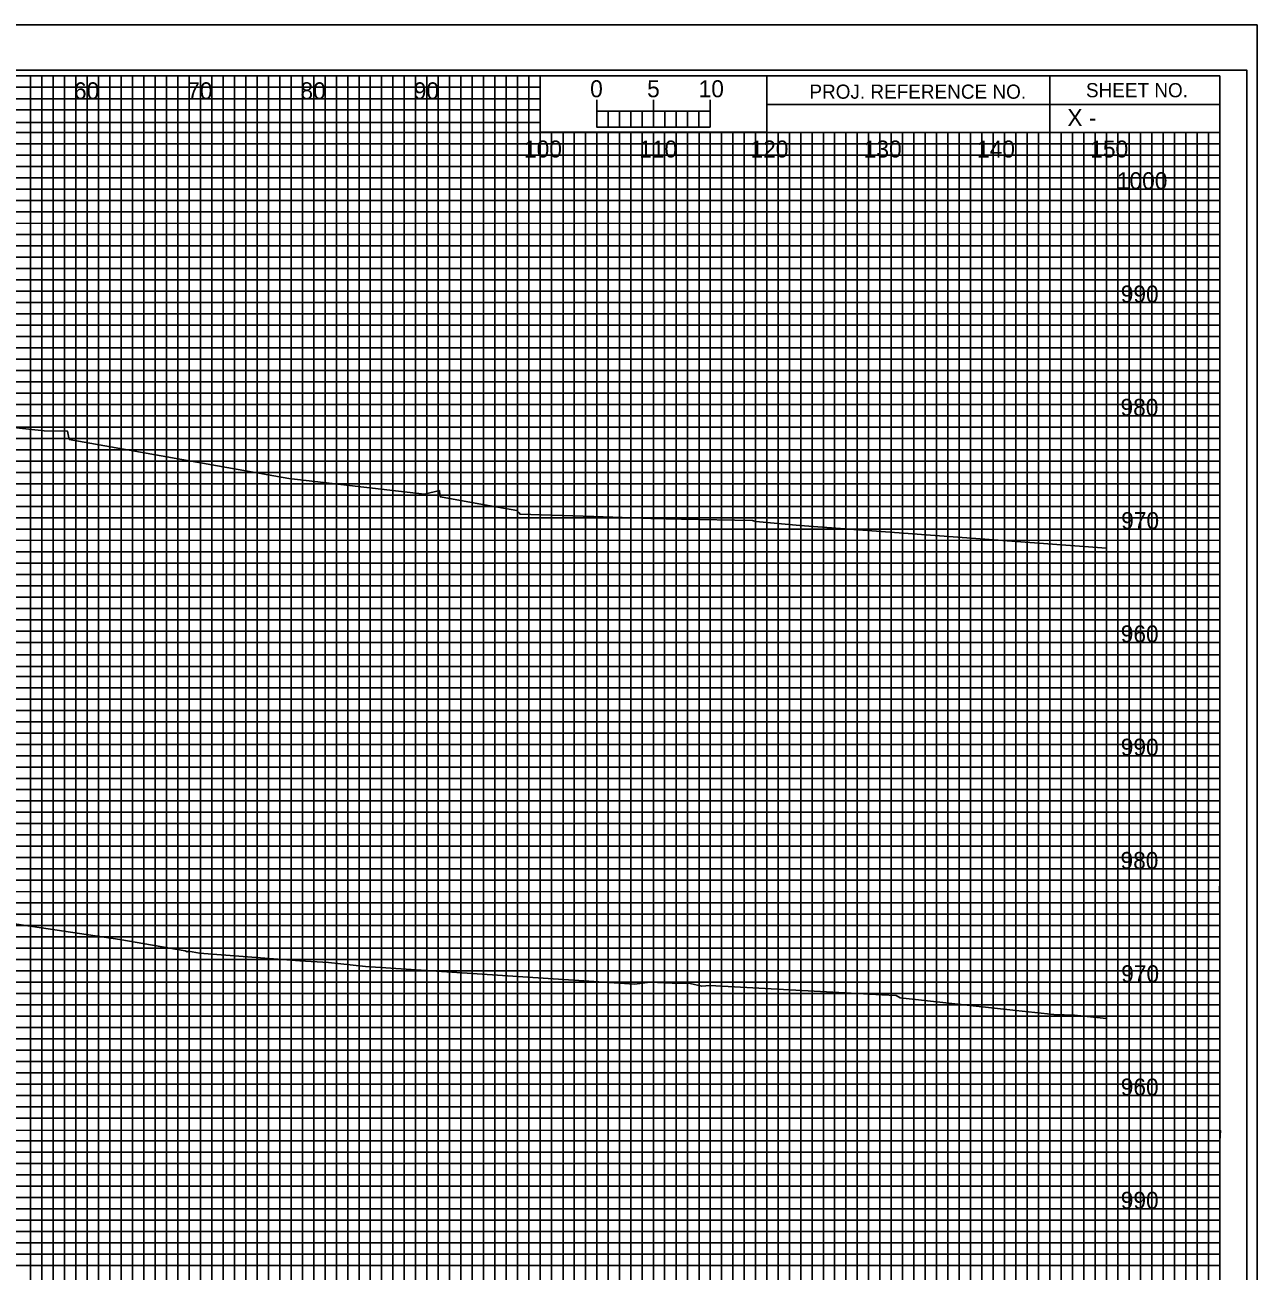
# Model space of a CAD drawing. Extents: x -13 to 760, y -5 to 1491.
# Drawn here: x 651.2 to 760, y 423.5 to 533.5 of the extents above; entities that cross this region are included whole.
import ezdxf

# ---------------------------------------------------------------- set-up
doc = ezdxf.new("R2010")
doc.units = 0
for name, color, linetype in [('Exist XS Ground Line', 7, 'Continuous'), ('Prop XS Elevation Labels', 7, 'Continuous'), ('Prop XS Offset Labels', 7, 'Continuous'), ('Sheet Cross Section CELL', 7, 'Continuous'), ('Sheet Cross Section Grid Major CELL', 7, 'Continuous'), ('Sheet Cross Section Grid Middle CELL', 7, 'Continuous'), ('Sheet Cross Section Grid Minor 1 CELL', 7, 'Continuous'), ('Sheet Cross Section Grid Minor 2 CELL', 7, 'Continuous'), ('Sheet Cross Section Scale CELL', 7, 'Continuous'), ('Sheet Cutting Line CELL', 7, 'Continuous'), ('Sheet DOT Grid CELL', 7, 'Continuous'), ('Sheet Plot Border Inside CELL', 7, 'Continuous'), ('Sheet Plot Border Outside CELL', 7, 'Continuous')]:
    doc.layers.add(name, color=color, linetype=linetype)

msp = doc.modelspace()

# ---------------------------------------------------------------- linework, layer by layer
at = {"layer": 'Exist XS Ground Line'}
for points in [[(650.47, 497.95), (652.91, 497.68), (654.95, 497.65), (655.11, 496.92), (655.12, 496.92), (674.49, 493.47), (686.48, 492.09), (687.8, 492.4), (687.85, 492.05), (687.89, 491.84), (691.27, 491.24), (694.63, 490.64), (694.64, 490.64), (694.85, 490.43), (694.93, 490.31), (701.44, 490.1), (706.46, 489.93), (709.19, 489.88), (715.46, 489.75), (715.74, 489.68), (719.63, 489.33), (746.7, 487.32)], [(650.47, 497.95), (652.91, 497.68), (654.95, 497.65), (655.11, 496.92), (655.12, 496.92), (674.49, 493.47), (686.48, 492.09), (687.8, 492.4), (687.85, 492.05), (687.89, 491.84), (691.27, 491.24), (694.63, 490.64), (694.64, 490.64), (694.85, 490.43), (694.93, 490.31), (701.44, 490.1), (706.46, 489.93), (709.19, 489.88), (715.46, 489.75), (715.74, 489.68), (719.63, 489.33), (746.7, 487.32)], [(644.72, 454.97), (659.59, 452.77), (665.36, 451.78), (665.52, 451.68), (665.65, 451.73), (666.61, 451.57), (675.47, 450.9), (678.02, 450.73), (681.26, 450.39), (705.04, 448.82), (706.4, 449), (708.35, 448.93), (709.95, 448.9), (710.96, 448.65), (711.67, 448.72), (726.88, 447.89), (728.12, 447.83), (728.47, 447.62), (738.7, 446.51), (742.05, 446.16), (743.88, 446.08), (744.99, 445.97), (746.7, 445.8)], [(644.72, 454.97), (659.59, 452.77), (665.36, 451.78), (665.52, 451.68), (665.65, 451.73), (666.61, 451.57), (675.47, 450.9), (678.02, 450.73), (681.26, 450.39), (705.04, 448.82), (706.4, 449), (708.35, 448.93), (709.95, 448.9), (710.96, 448.65), (711.67, 448.72), (726.88, 447.89), (728.12, 447.83), (728.47, 447.62), (738.7, 446.51), (742.05, 446.16), (743.88, 446.08), (744.99, 445.97), (746.7, 445.8)]]:
    msp.add_lwpolyline(points, dxfattribs=at)
at = {"layer": 'Sheet Cross Section CELL'}
for p, q in [((741.7, 529), (741.7, 524)), ((741.7, 524), (741.7, 529)), ((716.7, 526.5), (716.7, 524)), ((756.7, 526.49), (716.7, 526.49)), ((716.7, 524), (756.7, 524))]:
    msp.add_line(p, q, dxfattribs=at)
for points in [[(756.7, 529), (436.7, 529), (436.7, 319), (756.7, 319)], [(716.7, 529), (696.7, 529), (696.7, 524.03), (716.7, 524.03)], [(756.7, 529), (716.7, 529), (716.7, 524), (756.7, 524)]]:
    msp.add_lwpolyline(points, close=True, dxfattribs=at)
at = {"layer": 'Sheet Cross Section Grid Major CELL'}
for p, q in [((666.7, 529), (656.7, 529)), ((656.7, 529), (656.7, 319)), ((666.7, 319), (666.7, 529)), ((686.7, 529), (676.7, 529)), ((676.7, 529), (676.7, 319)), ((686.7, 319), (686.7, 529)), ((696.7, 529), (696.7, 319)), ((706.7, 319), (706.7, 524)), ((726.7, 524), (716.7, 524)), ((716.7, 524), (716.7, 319)), ((726.7, 319), (726.7, 524)), ((746.7, 524), (736.7, 524)), ((736.7, 524), (736.7, 319)), ((746.7, 319), (746.7, 524))]:
    msp.add_line(p, q, dxfattribs=at)
for points in [[(436.7, 519), (756.7, 519), (756.7, 509), (436.7, 509)], [(436.7, 499), (756.7, 499), (756.7, 489), (436.7, 489)], [(436.7, 479), (756.7, 479), (756.7, 469), (436.7, 469)], [(436.7, 459), (756.7, 459), (756.7, 449), (436.7, 449)], [(436.7, 439), (756.7, 439), (756.7, 429), (436.7, 429)]]:
    msp.add_lwpolyline(points, dxfattribs=at)
at = {"layer": 'Sheet Cross Section Grid Middle CELL'}
for points in [[(651.7, 319), (651.7, 529), (661.7, 529), (661.7, 319)], [(671.7, 319), (671.7, 529), (681.7, 529), (681.7, 319)], [(691.7, 319), (691.7, 529), (696.63, 529), (696.7, 529), (696.7, 524), (701.69, 524), (701.69, 319)], [(436.7, 524), (711.7, 524)], [(711.7, 319), (711.7, 524), (721.7, 524), (721.7, 319)], [(731.7, 319), (731.7, 524), (741.7, 524), (741.7, 319)], [(751.7, 319), (751.7, 524)], [(436.7, 504), (756.7, 504), (756.7, 514), (436.7, 514)], [(436.7, 484), (756.7, 484), (756.7, 494), (436.7, 494)], [(436.7, 464), (756.7, 464), (756.7, 474), (436.7, 474)], [(436.7, 444), (756.7, 444), (756.7, 454), (436.7, 454)], [(436.7, 424), (756.7, 424), (756.7, 434), (436.7, 434)]]:
    msp.add_lwpolyline(points, dxfattribs=at)
at = {"layer": 'Sheet Cross Section Grid Minor 1 CELL'}
for p, q in [((436.7, 528), (696.7, 528)), ((696.7, 528), (696.7, 526.98)), ((696.7, 526.98), (436.7, 526.98)), ((436.7, 526), (696.7, 526)), ((696.7, 526), (696.7, 524.89)), ((696.7, 524.89), (436.7, 524.89)), ((436.7, 523), (756.7, 523))]:
    msp.add_line(p, q, dxfattribs=at)
for points in [[(436.7, 522), (706.7, 522), (756.7, 522), (756.7, 521), (436.7, 521)], [(436.7, 520), (756.7, 520), (756.7, 518), (436.7, 518)], [(436.7, 517), (756.7, 517), (756.7, 516), (436.7, 515.98)], [(436.7, 515), (756.7, 515), (756.7, 513), (436.7, 513)], [(436.7, 512), (756.7, 512), (756.7, 511), (436.7, 511)], [(436.7, 510), (756.7, 510), (756.7, 508), (436.7, 508)], [(436.7, 507), (756.7, 507), (756.7, 506), (436.7, 506)], [(436.7, 505), (756.7, 505), (756.7, 503), (436.7, 503)], [(436.7, 502), (756.7, 502), (756.7, 501), (436.7, 501)], [(436.7, 500), (756.7, 500), (756.7, 498), (436.7, 498)], [(436.7, 497), (756.7, 497), (756.7, 496), (436.7, 496)], [(436.7, 495), (756.7, 495), (756.7, 492.95), (756.7, 492), (756.7, 491), (436.7, 491)], [(436.7, 493), (756.7, 493), (756.7, 492), (436.7, 492)], [(436.7, 490), (756.7, 490), (756.7, 488), (436.7, 488.03)], [(436.7, 488.03), (756.7, 488), (756.7, 487), (436.7, 487)], [(436.7, 486), (756.7, 486), (756.7, 485), (436.7, 485)], [(436.7, 483), (756.7, 483), (756.7, 482), (436.7, 482)], [(436.7, 481), (756.7, 481), (756.7, 480), (436.7, 480)], [(436.63, 477.89), (756.7, 477.89), (756.7, 476.88), (436.63, 476.88)], [(436.7, 476), (756.7, 476), (756.7, 475), (436.7, 475)], [(436.7, 473), (756.7, 473), (756.7, 472), (436.7, 472)], [(436.7, 471), (756.7, 471), (756.7, 470), (436.7, 470)], [(436.7, 468), (756.7, 468), (756.7, 467), (436.7, 467)], [(436.7, 466), (756.7, 466), (756.7, 465), (436.7, 465)], [(436.7, 463), (756.7, 463), (756.7, 462), (436.7, 462)], [(436.7, 461), (756.7, 461), (756.7, 460), (436.7, 460)], [(436.7, 458), (756.7, 458), (756.69, 456.98), (436.7, 457)], [(436.7, 456), (756.7, 456), (756.7, 455), (436.7, 455)], [(436.7, 453), (756.7, 453), (756.7, 452), (436.7, 452)], [(436.7, 451), (756.7, 451), (756.7, 450), (436.7, 450)], [(436.7, 448), (756.7, 448), (756.7, 447), (436.7, 447)], [(436.7, 446), (756.7, 446), (756.7, 445), (436.7, 445)], [(436.7, 443), (756.7, 443), (756.7, 442), (436.7, 442)], [(436.7, 441), (756.7, 441), (756.7, 440), (436.7, 440)], [(436.7, 438), (756.7, 438), (756.7, 437), (436.7, 437)], [(436.7, 435.99), (756.77, 435.91), (756.7, 435), (436.7, 435)], [(436.7, 433), (756.7, 433), (756.7, 432), (436.7, 432)], [(436.7, 431), (756.7, 431), (756.7, 430), (436.7, 430)], [(436.7, 428), (756.7, 428), (756.7, 427), (436.7, 427)], [(436.7, 426), (756.7, 426), (756.7, 425), (436.7, 425)]]:
    msp.add_lwpolyline(points, dxfattribs=at)
at = {"layer": 'Sheet Cross Section Grid Minor 2 CELL'}
for p, q in [((703.7, 524), (702.71, 524)), ((702.71, 524), (702.71, 319)), ((703.7, 319), (703.7, 524)), ((705.7, 524), (704.7, 524)), ((704.7, 524), (704.7, 319)), ((705.7, 319), (705.7, 524))]:
    msp.add_line(p, q, dxfattribs=at)
for points in [[(651.7, 319), (652.7, 319), (652.7, 529), (653.7, 529), (653.7, 319)], [(653.7, 319), (654.7, 319), (654.7, 529), (655.7, 529), (655.7, 319)], [(656.7, 319), (657.7, 319), (657.7, 529), (658.7, 529), (658.7, 319)], [(658.7, 319), (659.7, 319), (659.7, 529), (660.7, 529), (660.7, 319)], [(661.7, 319), (662.7, 319), (662.7, 529), (663.7, 529), (663.7, 319)], [(663.7, 319), (664.7, 319), (664.7, 529), (665.7, 529), (665.7, 319)], [(666.7, 319), (667.7, 319), (667.7, 529), (668.7, 529), (668.7, 319)], [(668.7, 319), (669.7, 319), (669.7, 529), (670.7, 529), (670.7, 319)], [(671.7, 319), (672.7, 319), (672.7, 529), (673.7, 529), (673.7, 319)], [(673.7, 319), (674.7, 319), (674.7, 529), (675.7, 529), (675.7, 319)], [(676.7, 319), (677.7, 319), (677.7, 529), (678.7, 529), (678.7, 319)], [(678.7, 319), (679.7, 319), (679.7, 529), (680.7, 529), (680.7, 319)], [(681.7, 319), (682.7, 319), (682.7, 529), (683.7, 529), (683.7, 319)], [(683.7, 319), (684.7, 319), (684.7, 529), (685.7, 529), (685.7, 319)], [(686.7, 319), (687.7, 319), (687.7, 529), (688.7, 529), (688.7, 319)], [(688.7, 319), (689.7, 319), (689.7, 529), (690.7, 529), (690.7, 319)], [(691.7, 319), (692.7, 319), (692.7, 529), (693.7, 529), (693.7, 319)], [(693.7, 319), (694.7, 319), (694.7, 529), (695.7, 529), (695.7, 319)], [(696.7, 319), (697.7, 319), (697.7, 524), (698.72, 524), (698.72, 319)], [(698.7, 319), (699.7, 319), (699.7, 524), (700.69, 524), (700.69, 319)], [(706.7, 319), (707.68, 319), (707.68, 524), (708.7, 524), (708.7, 319)], [(708.7, 319), (709.7, 319), (709.7, 524), (710.75, 524), (710.75, 319)], [(711.7, 319), (712.7, 319), (712.7, 524), (713.7, 524), (713.7, 319)], [(713.7, 319), (714.7, 319), (714.7, 524), (715.7, 524), (715.7, 319)], [(716.7, 319), (717.7, 319), (717.7, 524), (718.7, 524), (718.7, 319)], [(718.7, 319), (719.7, 319), (719.7, 524), (720.7, 524), (720.7, 319)], [(721.7, 319), (722.7, 319), (722.7, 524), (723.7, 524), (723.7, 319)], [(723.7, 319), (724.7, 319), (724.7, 524), (725.7, 524), (725.7, 319)], [(726.7, 319), (727.7, 319), (727.7, 524), (728.7, 524), (728.7, 319)], [(728.7, 319), (729.7, 319), (729.7, 524), (730.7, 524), (730.7, 319)], [(731.7, 319), (732.7, 319), (732.7, 524), (733.7, 524), (733.7, 319)], [(733.7, 319), (734.7, 319), (734.7, 524), (735.7, 524), (735.7, 319)], [(736.7, 319), (737.7, 319), (737.7, 524), (738.7, 524), (738.7, 319)], [(738.7, 319), (739.7, 319), (739.7, 524), (740.7, 524), (740.7, 319)], [(741.7, 319), (742.7, 319), (742.7, 524), (743.7, 524), (743.7, 319)], [(743.7, 319), (744.7, 319), (744.7, 524), (745.7, 524), (745.7, 319)], [(746.7, 319), (747.7, 319), (747.7, 524), (748.7, 524), (748.7, 319)], [(748.7, 319), (749.7, 319), (749.7, 524), (750.7, 524), (750.7, 319)], [(751.7, 319), (752.7, 319), (752.7, 524), (753.7, 524), (753.7, 319)], [(753.7, 319), (754.7, 319), (754.7, 524), (755.7, 524), (755.7, 319)]]:
    msp.add_lwpolyline(points, dxfattribs=at)
at = {"layer": 'Sheet Cross Section Scale CELL'}
for p, q in [((701.7, 524.49), (701.7, 526.9)), ((701.7, 525.9), (701.7, 526.9)), ((706.7, 524.49), (706.7, 526.9)), ((711.7, 524.49), (711.7, 526.9)), ((711.7, 525.9), (711.7, 526.9))]:
    msp.add_line(p, q, dxfattribs=at)
for points in [[(711.7, 525.9), (701.7, 525.9), (701.7, 524.49), (711.7, 524.49)], [(701.7, 525.9), (702.7, 525.9), (702.7, 524.49), (701.7, 524.49)], [(703.7, 525.9), (704.7, 525.9), (704.7, 524.49), (703.7, 524.49)], [(705.7, 525.9), (706.7, 525.9), (706.7, 524.49), (705.7, 524.49)], [(707.7, 525.9), (708.7, 525.9), (708.7, 524.49), (707.7, 524.49)], [(709.7, 525.9), (710.7, 525.9), (710.7, 524.49), (709.7, 524.49)]]:
    msp.add_lwpolyline(points, close=True, dxfattribs=at)
at = {"layer": 'Sheet Cutting Line CELL'}
msp.add_line((760, 533.5), (423.3, 533.5), dxfattribs=at)
at = {"layer": 'Sheet DOT Grid CELL'}
for p, q in [((656.7, 319), (656.7, 529)), ((666.7, 319), (666.7, 529)), ((676.7, 319), (676.7, 529)), ((686.7, 319), (686.7, 529)), ((696.7, 319), (696.7, 523.69)), ((706.7, 319), (706.7, 523.69)), ((716.7, 319), (716.7, 523.69)), ((726.7, 319), (726.7, 523.69)), ((736.7, 319), (736.7, 523.69)), ((746.7, 319), (746.7, 523.69)), ((436.7, 519), (756.7, 519)), ((436.7, 509), (756.7, 509)), ((436.7, 499), (756.7, 499)), ((436.7, 489), (756.7, 489)), ((436.7, 479), (756.7, 479)), ((436.7, 469), (756.7, 469)), ((436.7, 459), (756.7, 459)), ((436.7, 449), (756.7, 449)), ((436.7, 439), (756.7, 439)), ((436.7, 429), (756.7, 429))]:
    msp.add_line(p, q, dxfattribs=at)
at = {"layer": 'Sheet Plot Border Inside CELL'}
msp.add_lwpolyline([(425.9, 318.5), (759.1, 318.5), (759.1, 529.5), (425.9, 529.5)], close=True, dxfattribs=at)
at = {"layer": 'Sheet Plot Border Outside CELL'}
msp.add_lwpolyline([(423.3, 314.5), (760, 314.5), (760, 533.5), (423.3, 533.5)], close=True, dxfattribs=at)

# ---------------------------------------------------------------- texts
at = {"layer": 'Prop XS Elevation Labels'}
for s, p in [('1000', (747.62, 519)), ('990', (747.96, 509)), ('980', (747.94, 499)), ('970', (748, 489)), ('960', (747.96, 479)), ('990', (747.96, 469)), ('980', (747.94, 459)), ('970', (748, 449)), ('960', (747.96, 439)), ('990', (747.96, 429))]:
    msp.add_text(s, height=1.5, dxfattribs=at).set_placement(p)
at = {"layer": 'Prop XS Offset Labels'}
for s, p in [('60', (655.53, 526.94)), ('70', (665.53, 526.94)), ('80', (675.53, 526.94)), ('90', (685.53, 526.94)), ('100', (695.27, 521.8)), ('110', (705.45, 521.8)), ('120', (715.27, 521.8)), ('130', (725.27, 521.8)), ('140', (735.27, 521.8)), ('150', (745.27, 521.8))]:
    msp.add_text(s, height=1.5, dxfattribs=at).set_placement(p)
at = {"layer": 'Sheet Cross Section CELL'}
for s, height, p in [('PROJ. REFERENCE NO.', 1.25, (720.47, 526.99)), ('SHEET NO.', 1.25, (744.89, 527.12)), ('X - ', 1.5, (743.25, 524.57))]:
    msp.add_text(s, height=height, dxfattribs=at).set_placement(p)
at = {"layer": 'Sheet Cross Section Scale CELL'}
for s, p in [('0', (701.11, 527.12)), ('5', (706.14, 527.12)), ('10', (710.69, 527.12))]:
    msp.add_text(s, height=1.5, dxfattribs=at).set_placement(p)

doc.saveas('drawing.dxf')
